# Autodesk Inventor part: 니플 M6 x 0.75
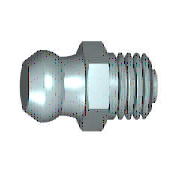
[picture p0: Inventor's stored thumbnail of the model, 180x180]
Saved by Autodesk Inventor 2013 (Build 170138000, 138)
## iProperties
IsCustomPart: 1
Created: 2012-02
Part Number: 니플 M6 x 0.75
Material: 강철, 연강
Description: 윤활 니플, 원추 유형 A
Document SubType Name: Modeling
Standard: JIS B 1575
Designer: mduedu
Standards Organization: JIS
Language: ko-KR
Size Designation: MT 6 x 0.75
Categories: <MemberInstance><Categories><Category DisplayName="기타 부품" InternalName="5aa15e00-363f-49f2-933f-16f664388e3f" Mnemonic="OTHER"><Category DisplayName="그리스 부속품" I
Density: 7.86 g/cm^3
Mass: 3.2546 g
Surface Area: 3.29319 cm^2
Volume: 0.414071 cm^3
Author: mduedu
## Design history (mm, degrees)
sketch "스케치1"
  geometry: L1 (-8.8, 0)-(-8.8, 2.4); L2 (-8.8, 2.4)-(-7.335, 3.202); L3 (-8.8, 0)-(4.7, 0); L4 (4.7, 0)-(4.7, 1.5); L5 (4.7, 1.5)-(4, 1.5); L6 (4, 1.5)-(4, 3); L7 (4, 3)-(0, 3); L8 (-11.5, 0)-(7.4, 0) reference; L9 (0, -1.733)-(0, 10.398) reference; L10 (-3, 3.5)-(0, 3.5); L11 (0, 3.5)-(0, 3); A1 r 3.3 centre (-6.535, 0) between (-4.789, 2.8) and (-7.335, 3.202); A2 r 6 centre (-6.053, 8.665) between (-4.789, 2.8) and (-3, 3.5)
  constraints: 18 end point, 5 perpendicular, 4 point on circle, 2 centre point, 2 parallel, 2 point on line, 1 collinear, 1 vertical
  dimensions: "d0" = 13.5 distance between parallel lines of L1 L4 (= GL); "d1" = 5.6 diameter of A1.start L3 (= KGB2); "d2" = 0.7 distance between parallel lines of L4 L6 (= PHH); "d3" = 3 diameter of L5 L3 (= 0.5 x NND); "d4" = 6 diameter of L7 L3 (= NND); "d5" = 6.6 dimension on A1 L3 (= KR); "d6" = 4.8 diameter of L1.end L3 (= KGB1); "d7" = 6 radius of A2 (= RBN); "d11" = 7 diameter of L10.start L3 (= SW); "d14" = 3 distance of L10.start L10.end (= KOH); "d15" = 4 distance between parallel lines of L6 L11 (= NLG); "d61" = 7.33505 distance from line of L9 L2.end (computed from KGB1, KR, PHH, GL, NLG, VERS); "d62" = 6.53505 distance from line of L9 A1.centre (computed from NLG, GL, PHH, KR, KGB1)
revolve "본체" sketch "스케치1" stored, may be unused: angle "d25" = 90 deg
sketch "스케치2"
  geometry: L1 (2.021, 3.5)-(4.041, 0); L2 (4.041, 0)-(2.021, -3.5); L3 (2.021, -3.5)-(-2.021, -3.5); L4 (-2.021, -3.5)-(-4.041, 0); L5 (-4.041, 0)-(-2.021, 3.5); L6 (-2.021, 3.5)-(2.021, 3.5); C1 r 3.5 at (0, 0) reference; 1 further point
  constraints: 12 end point, 1 coincident, 1 horizontal, 1 tangent, 11 other
extrude "머리" join sketch "스케치2" distance "d17" = 3 (= KOH); taper "d18" = 0 deg
sketch "스케치3"
  geometry: L1 (2.687, 4.041)-(3, 4.041); L2 (3, 4.041)-(3, 3.5); L3 (3, 3.5)-(2.687, 4.041); L4 (0.313, 4.041)-(0, 4.041); L5 (0, 4.041)-(0, 3.5); L6 (0, 3.5)-(0.313, 4.041); L7 (3.6, 0)-(-0.6, 0) reference; L8 (0, 4.041)-(0, 2.021) reference; L9 (0, 4.041)-(3, 4.041) reference; L10 (3, 3.031)-(3, 4.041) reference
  constraints: 12 end point, 4 collinear, 3 perpendicular, 1 horizontal
  dimensions: "d19" = 3.5 distance from line of L5.end L7 (= 0.5 x SW); "d20" = 3.5 distance from line of L2.end L7 (= 0.5 x SW); "d21" = 30 deg angle of L6 L5; "d22" = 30 deg angle of L2 L3
revolve "모따기1" sketch "스케치3" stored, may be unused: angle "d56" = 90 deg
body "Solid1"
fillet "모깎기1" dims "d8" = 0.2 (= RR)
feature "스레드1" dims "d9" = 3.53991 (= NLG - GAL), "d10" = 0
chamfer "모따기2" distance "d23" = 0.46009 (= -0.5 x GD1 + 0.5 x NND); stored, may be unused: angle "d24" = 45 deg, second distance "d59" = 0.46009 (= -0.5 x GD1 + 0.5 x NND)
other parameters: "NLG" = 4 [user parameter; used in 4 equation terms], "GL" = 13.5 [user parameter; used in 3 equation terms], "NND" = 6 [user parameter; used in 4 equation terms], "KGB1" = 4.8 [user parameter; used in 3 equation terms], "KGB2" = 5.6 [user parameter; used in 1 equation term], "VERS" = 0.8 [user parameter; used in 1 equation term], "KR" = 6.6 [user parameter; used in 3 equation terms], "RBN" = 6 [user parameter; used in 1 equation term], "SW" = 7 [user parameter; used in 3 equation terms], "KOH" = 3 [user parameter; used in 2 equation terms], "GAL" = 0.46009 (= 0.61345 x PTC) [user parameter; used in 1 equation term], "FAWI" = 45 deg [user parameter], "PHH" = 0.7 [user parameter; used in 3 equation terms], "GD1" = 5.07983 (= THREADDIA - 1.2269 x PTC) [user parameter; used in 2 equation terms], "RR" = 0.2 [user parameter; used in 1 equation term], "d12" = 0, "d13" = 0, "GUL" = 0.46009 (= 0.61345 x PTC) [user parameter], "TPU" = 13.33333 (computed from PTC) [user parameter], "DULO" = 1.5 [user parameter], "PTC" = 0.75 [user parameter; used in 4 equation terms], "GEL" = 4 [user parameter], "THREADDIA" = 6 [user parameter; used in 1 equation term], "TOA" = 30 deg [user parameter]
